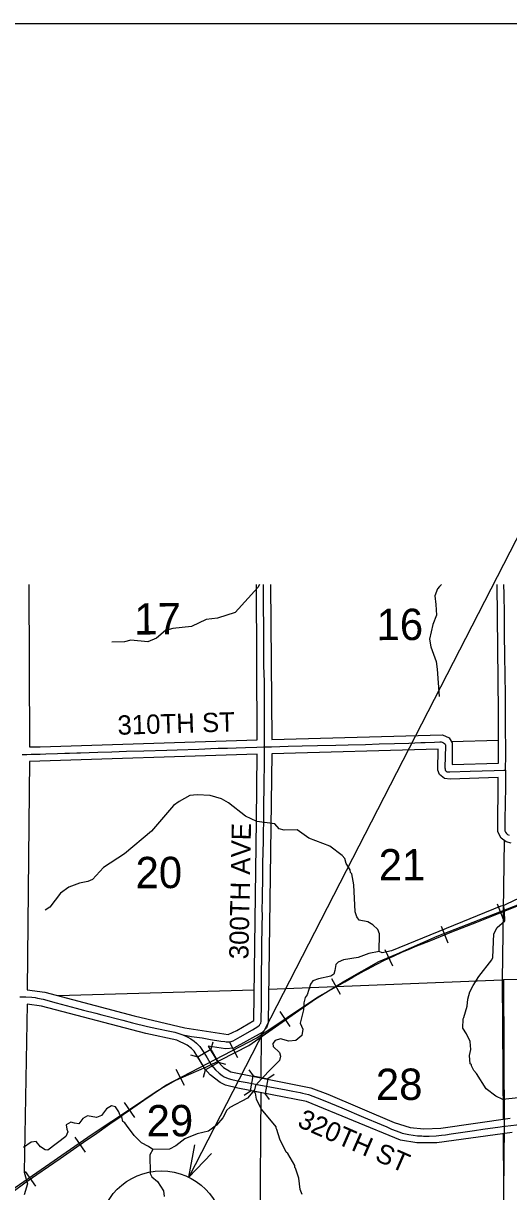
# Model space of a CAD drawing. Extents: x 10133 to 81668, y 7924 to 11018.
# Drawn here: x 11454 to 11756, y 9217 to 9944 of the extents above; entities that cross this region are included whole.
import ezdxf

# ---------------------------------------------------------------- set-up
doc = ezdxf.new("R2010")
doc.units = 0
for name, color, linetype in [('SheetBorder', 7, 'Continuous'), ('tdCoCityStreetMajor', 7, 'Continuous'), ('tdCoCityStreetMinor', 7, 'Continuous'), ('tdCoHydroRiver', 7, 'Continuous'), ('tdCoPriNonDiv', 7, 'Continuous'), ('tdCoRRCL', 7, 'Continuous'), ('tdCoRROwnerTxt', 7, 'Continuous'), ('tdCoShieldCoRte', 7, 'Continuous'), ('tdCoShieldStRte', 7, 'Continuous'), ('tdCoStrucNonDivPri', 7, 'Continuous'), ('tdCoSurfGravel', 7, 'Continuous'), ('tdCoTwpBndryShd', 7, 'Continuous')]:
    doc.layers.add(name, color=color, linetype=linetype)

msp = doc.modelspace()

# ---------------------------------------------------------------- linework, layer by layer
at = {"layer": 'SheetBorder'}
for p, q in [((11832.54, 9762.18), (11557.09, 9226.18)), ((11557.09, 9226.18), (11560.85, 9246.27)), ((11557.09, 9226.18), (11571.23, 9240.94))]:
    msp.add_line(p, q, dxfattribs=at)
msp.add_lwpolyline([(10132.52, 9944.02), (13267.53, 9944.02), (13267.53, 7924.02), (10132.52, 7924.02)], close=True, dxfattribs=at)
msp.add_circle((11540.08, 9191.25), 38.85, dxfattribs=at)
at = {"layer": 'tdCoCityStreetMajor'}
msp.add_lwpolyline([(11604.29, 9506.89), (11604.27, 9513.52), (11604.25, 9522.6), (11604.27, 9534.65), (11603.93, 9544.27), (11603.78, 9555.72), (11603.75, 9572.71), (11603.63, 9577.17), (11603.56, 9588), (11603.56, 9593.54), (11603.56, 9594.91)], dxfattribs=at)
at = {"layer": 'tdCoCityStreetMinor'}
for points in [[(11754.35, 9479.31), (11754.38, 9481.04), (11754.55, 9487.28), (11754.5, 9493.19), (11754.4, 9504.74), (11754.35, 9515.78), (11754.25, 9526.71), (11754.1, 9538.35), (11753.93, 9550.8), (11753.78, 9563.9), (11753.59, 9576.47), (11753.41, 9588.95), (11753.35, 9594.91)], [(11604.23, 9493.82), (11604.15, 9495.44), (11604.32, 9501.58), (11604.3, 9504.77), (11604.29, 9506.89)], [(11453.46, 9489.11), (11454.39, 9489.13), (11456.22, 9489.2), (11459.03, 9489.38), (11464.63, 9489.35), (11468.18, 9489.57), (11475.33, 9489.75), (11479.99, 9489.94), (11482.8, 9489.99), (11487.46, 9490.09), (11489.68, 9490.14), (11500.39, 9490.61), (11509.12, 9490.73), (11518.27, 9491.13), (11529.17, 9491.4), (11543.35, 9491.92), (11549.91, 9492.09), (11563.27, 9492.48), (11570.84, 9492.88), (11575.36, 9493.05), (11581.18, 9493.15), (11586.63, 9493.32), (11592.37, 9493.52), (11599.55, 9493.77), (11603.64, 9493.82), (11604.23, 9493.82)], [(11553.41, 9314.77), (11555.74, 9314.34), (11558.8, 9313.77), (11565.46, 9312.81), (11570.64, 9311.94), (11577.1, 9310.88), (11579.46, 9310.54), (11580.4, 9310.46), (11581.54, 9310.44), (11582.57, 9310.44), (11583.46, 9310.61), (11584.72, 9311.11), (11589.11, 9313.45), (11596.75, 9317.79), (11600.1, 9319.84), (11601.07, 9320.75), (11601.63, 9321.61), (11601.88, 9322.06), (11602.13, 9323.16), (11602.23, 9325.29), (11602.3, 9331.8), (11602.32, 9341.71), (11602.32, 9346.42), (11602.42, 9353.32), (11602.5, 9362.75), (11602.62, 9372.58), (11602.72, 9379.84), (11602.82, 9383.14), (11602.99, 9388.74), (11602.87, 9393.15), (11602.99, 9398.92), (11603.06, 9403.85), (11603.26, 9409.55), (11603.29, 9415.91), (11603.31, 9422.42), (11603.38, 9427.48), (11603.53, 9436.16), (11603.61, 9440.13), (11603.75, 9448.1), (11603.88, 9459.14), (11603.95, 9467.5), (11603.98, 9472.19), (11604.15, 9482.57), (11604.3, 9492.58), (11604.23, 9493.82)], [(11604.23, 9493.82), (11605.29, 9493.82), (11608.57, 9493.96), (11618.93, 9494.31), (11627.73, 9494.51), (11637.2, 9494.65), (11648.7, 9495.02), (11656.27, 9495.07), (11667.09, 9495.44), (11675.58, 9495.69), (11685.14, 9496.04), (11694.02, 9496.23), (11701.52, 9496.53), (11704.21, 9496.6), (11710.05, 9496.87), (11713.5, 9497), (11714.29, 9497), (11714.96, 9496.82), (11715.65, 9496.5), (11716.24, 9496.06), (11716.64, 9495.52), (11716.86, 9494.88), (11716.96, 9494.11), (11716.81, 9488.02), (11716.54, 9480.84), (11716.64, 9480.15), (11716.81, 9479.44), (11717.4, 9478.82), (11718.02, 9478.43), (11719.67, 9478.4), (11732.27, 9478.75), (11747.31, 9479.27), (11753.23, 9479.37), (11754.35, 9479.31)], [(11754.35, 9479.31), (11754.33, 9477.88), (11754.23, 9469.59), (11754.06, 9458), (11753.96, 9449.32), (11753.88, 9442.94), (11753.98, 9441.68), (11754.33, 9440.89), (11754.94, 9440.1), (11755.61, 9439.46), (11756.57, 9438.94)], [(11452, 9338.42), (11453.11, 9338.45), (11455.63, 9338.35), (11459.28, 9338.15), (11461.35, 9337.93), (11462.83, 9337.66), (11466.38, 9336.94), (11474.59, 9334.7), (11477.58, 9333.88), (11486.9, 9331.44), (11491.63, 9330.18), (11499.18, 9328.16), (11503.03, 9327.1), (11515.95, 9323.85), (11521.99, 9322.24), (11531.48, 9319.85), (11537.21, 9318.62), (11545.25, 9317.04), (11548.45, 9316.33), (11550.92, 9315.68), (11553.41, 9314.77)], [(11553.41, 9314.77), (11556.1, 9313.47), (11558.36, 9312.23), (11560.46, 9310.8), (11561.89, 9309.54), (11563.96, 9307.45), (11566.45, 9303.7), (11568.5, 9300.52), (11570.94, 9296.15), (11572.52, 9294.35), (11573.73, 9292.92), (11575.92, 9290.95), (11577.97, 9289.54), (11579.15, 9288.71), (11581.69, 9287.57), (11583.81, 9286.86), (11588.48, 9285.89), (11593.36, 9285.03), (11601.79, 9283.53), (11609.81, 9282.05), (11617.72, 9280.57), (11621.92, 9279.73), (11626.38, 9278.92), (11627.88, 9278.5), (11631.63, 9277.53), (11634.25, 9276.62), (11637.11, 9275.59), (11641.89, 9273.69), (11652.32, 9269.25), (11665.91, 9263.48), (11676.83, 9258.92), (11680.41, 9257.49), (11683.32, 9256.13), (11688.5, 9254.23), (11690.05, 9253.64), (11694.05, 9252.65), (11696.88, 9252.23), (11699.52, 9251.99), (11702.21, 9251.84), (11703.3, 9251.76), (11706.72, 9251.79), (11711.14, 9251.94), (11714.39, 9252.23), (11717.01, 9252.53), (11720.53, 9253.14), (11735.03, 9255.29), (11740.26, 9255.98), (11751.01, 9257.49), (11753.46, 9257.83)]]:
    msp.add_lwpolyline(points, dxfattribs=at)
at = {"layer": 'tdCoHydroRiver'}
for points in [[(11601.23, 9594.91), (11600.02, 9593.14), (11586.08, 9577.51), (11575.01, 9574.01), (11567.92, 9573.18), (11558.76, 9568.77), (11547.17, 9567.62), (11542.69, 9566.37), (11537.09, 9561.54), (11531.68, 9559.31), (11521.01, 9560.32), (11517, 9559.3), (11509.2, 9558.94)], [(11714.45, 9594.91), (11713.2, 9593.62), (11712.04, 9592.18), (11710.22, 9587.88), (11711.02, 9582.45), (11711.37, 9575.83), (11709.09, 9570.11), (11706.88, 9560.83), (11707.91, 9556.11), (11711.14, 9546.93), (11711.69, 9542.21), (11712.93, 9525.18)], [(11675.57, 9366.61), (11675.86, 9377.51), (11674.87, 9380.33), (11671.74, 9383.12), (11668.63, 9384.97), (11663.17, 9386.06), (11661.71, 9388.16), (11660.71, 9391.23), (11659.96, 9408.03), (11658.66, 9414.87), (11657.7, 9415.8), (11657.67, 9417.46), (11655, 9421.44), (11654.24, 9424.5), (11652.55, 9426.37), (11644.87, 9432.16), (11631.76, 9437.15), (11624.58, 9442.24), (11616.53, 9442.1), (11613.43, 9443), (11610.78, 9446.03), (11599.39, 9447.5), (11592.47, 9450.7), (11581.91, 9459.05), (11577.37, 9461.57), (11570.47, 9463.59), (11562.41, 9464.16), (11557.68, 9463.61), (11551.11, 9459.95), (11547.6, 9457.52), (11533.9, 9441.43), (11517.09, 9427.41), (11503.97, 9418.9), (11497.23, 9411.45), (11494.17, 9410.21), (11488.98, 9409.18), (11482.39, 9406.7), (11477.24, 9402.83), (11470.52, 9394.19), (11467.71, 9392.25)], [(11775.19, 9404.04), (11760.54, 9398.66), (11753.23, 9395.15)], [(11753.23, 9395.15), (11751.34, 9394.88), (11683.38, 9366.98), (11677.48, 9365.7), (11675.57, 9366.61)], [(11762.11, 9275.48), (11752.65, 9274.61), (11748.36, 9276.67), (11742.36, 9281.07), (11736.28, 9290.67), (11734.59, 9292.54), (11733.12, 9295.36), (11733.11, 9296.3), (11732.39, 9296.76), (11731.83, 9301.96), (11732.72, 9305.53), (11732.4, 9310.5), (11729.95, 9315.43), (11727.76, 9318.94), (11727.9, 9324.63), (11728.35, 9325.59), (11730.37, 9332.49), (11730.77, 9336.99), (11732.11, 9341.51), (11734.18, 9345.34), (11737.63, 9351.08), (11745.75, 9361.4), (11746.44, 9362.83), (11747.14, 9377.52), (11749.2, 9381.58), (11753.87, 9385.69), (11753.77, 9391.37), (11753.51, 9392.78), (11753.23, 9395.15)], [(11675.57, 9366.61), (11669.2, 9365.32), (11662.61, 9362.84), (11653.4, 9361.5), (11650.11, 9360.03), (11648.71, 9358.58), (11648.07, 9354.78), (11647.4, 9352.4), (11645.52, 9351.19), (11637.97, 9349.64), (11634.44, 9348.4), (11632.82, 9346.24), (11630.8, 9339.58), (11629.64, 9337.9), (11628.75, 9334.57), (11628.59, 9330.3), (11626.36, 9321.98), (11628.08, 9318.22), (11627.43, 9314.42), (11623.7, 9311.28), (11619.44, 9310.73), (11614.21, 9312.3), (11610.91, 9311.3), (11609.52, 9309.38), (11609.55, 9307.49), (11613.64, 9303.77), (11614.15, 9301.41), (11613.49, 9298.79), (11608.37, 9293.5), (11602.55, 9287.48), (11598.6, 9283.15), (11597.93, 9280.54)], [(11597.93, 9280.54), (11593.76, 9275.26), (11582.72, 9269.62), (11580.85, 9267.94), (11578.33, 9263.16), (11574.38, 9258.59), (11569.47, 9254.72), (11562.4, 9253.18), (11554.64, 9249.97), (11549.03, 9245.62), (11545.03, 9243.65), (11534.62, 9243.48)], [(11627.67, 9215.44), (11626.44, 9218.5), (11625.61, 9225.59), (11623.61, 9231.71), (11623.13, 9232.18), (11623.11, 9233.36), (11618.72, 9240.87), (11617.76, 9241.8), (11613.84, 9249.78), (11611.84, 9255.91), (11611.59, 9256.61), (11611.58, 9257.56), (11608.67, 9261.06), (11602.15, 9268.77), (11599.21, 9274.64), (11598.67, 9278.42), (11597.95, 9279.11), (11597.93, 9280.54)], [(11534.62, 9243.48), (11531.98, 9245.33), (11527.68, 9247.63), (11523.11, 9252.05), (11518.26, 9258.6), (11517.29, 9260), (11516.09, 9260.93), (11515.33, 9263.76), (11514.13, 9264.92), (11513.63, 9266.81), (11511.44, 9269.85), (11509.06, 9270.52), (11505.78, 9268.81), (11502.77, 9264.49), (11499.71, 9263.26), (11494.01, 9264.35), (11491.2, 9262.64), (11488.65, 9259.28), (11486.04, 9259.71), (11483.66, 9260.38), (11480.85, 9258.68), (11481.13, 9256.08), (11481.87, 9254.43), (11480.49, 9251.57), (11469.27, 9243.09), (11467.61, 9243.3), (11464.74, 9245.15), (11462.08, 9248.42), (11459.01, 9247.89), (11454.09, 9244.73)], [(11534.62, 9243.48), (11532.78, 9240.13), (11532.98, 9228.53), (11534.19, 9226.42), (11537.56, 9223.4), (11541.44, 9217.78), (11541.74, 9214.24)]]:
    msp.add_lwpolyline(points, dxfattribs=at)
at = {"layer": 'tdCoPriNonDiv'}
msp.add_line((11457.5, 9594.91), (11457.98, 9493.82), dxfattribs=at)
for points in [[(11457.98, 9493.82), (11464.5, 9493.85), (11599.73, 9498.27), (11599.22, 9594.91)], [(11608.07, 9594.91), (11608.73, 9498.47), (11715.05, 9501.43), (11719.2, 9499.45), (11721.11, 9496.35), (11721.12, 9482.94)], [(11721.12, 9482.94), (11749.95, 9483.81), (11749.85, 9515.75), (11749.02, 9594.91)], [(11757.74, 9434.03), (11754.7, 9434.85), (11751.6, 9437.09), (11749.54, 9440.95), (11749.79, 9474.81), (11719.79, 9473.91), (11716.22, 9474.3), (11713.3, 9476.62), (11712.22, 9479.31), (11712.42, 9492.46), (11608.75, 9489.47), (11606.52, 9322.19), (11605.39, 9319.14), (11602.71, 9316.17), (11585.1, 9306.42), (11580.05, 9305.98), (11569.25, 9307.61), (11574.64, 9298.76), (11578.71, 9294.49), (11583.33, 9291.77), (11633.11, 9281.78), (11643.65, 9277.83), (11685.05, 9260.29), (11694.92, 9257.07), (11703.43, 9256.26), (11713.94, 9256.71), (11757.29, 9262.91)], [(11586.94, 9317.39), (11597.65, 9323.76), (11599.26, 9448.16), (11599.75, 9489.27), (11457.94, 9484.8), (11457.66, 9466.01), (11456.51, 9342.8), (11467.57, 9341.28), (11523.12, 9326.6), (11554.6, 9319.13), (11581.58, 9314.94), (11586.94, 9317.39)], [(11758.54, 9254), (11711.55, 9247.46), (11699.1, 9247.51), (11688.97, 9249.27), (11630.33, 9273.22), (11587.57, 9281.49), (11579.86, 9283.46), (11576.55, 9285.03), (11570.5, 9289.79), (11567.36, 9293.43), (11560.46, 9304.6), (11558.8, 9306.27), (11556.02, 9308.39), (11549.57, 9311.39), (11530.39, 9315.49), (11465.34, 9332.56), (11456.41, 9333.8), (11454.66, 9229.41), (11456.75, 9222.11), (11454.63, 9215.25)]]:
    msp.add_lwpolyline(points, dxfattribs=at)
at = {"layer": 'tdCoRRCL'}
for p, q in [((11753.37, 9385.52), (11749.23, 9395.98)), ((11718.51, 9371.72), (11714.36, 9382.18)), ((11684.2, 9357.39), (11679.48, 9367.6)), ((11651.61, 9339.79), (11646.09, 9349.6)), ((11620.3, 9320.01), (11614.03, 9329.35)), ((11587.68, 9300.38), (11582.51, 9310.37)), ((11568.06, 9294.84), (11577.07, 9299.13)), ((11554.37, 9283.15), (11549.2, 9293.14)), ((11523.46, 9263.32), (11517.06, 9272.57)), ((11492.71, 9241.84), (11486.33, 9251.1)), ((11461.92, 9220.55), (11455.42, 9229.74))]:
    msp.add_line(p, q, dxfattribs=at)
for points in [[(11577.07, 9299.13), (11594.5, 9308.16), (11635.99, 9337.16), (11654.28, 9348.37), (11675.39, 9360.38), (11686.92, 9365.1), (11711.76, 9376.15), (11777.93, 9401.93)], [(11447.66, 9217.37), (11455.03, 9222.58), (11462.41, 9227.79), (11477.01, 9237.85), (11491.62, 9247.92), (11499.76, 9253.64), (11507.9, 9259.36), (11514.29, 9263.8), (11516.19, 9265.12), (11518.09, 9266.44), (11529.06, 9274.03), (11540.03, 9281.62), (11542.86, 9283.52), (11599.49, 9312.82), (11637.31, 9338.2), (11645.76, 9342.96), (11654.22, 9347.72), (11659.29, 9350.63), (11664.36, 9353.54), (11666.39, 9354.62), (11668.41, 9355.7), (11673.86, 9358.51), (11679.3, 9361.32), (11684.53, 9363.74), (11689.76, 9366.16), (11693.87, 9367.89), (11697.98, 9369.62), (11702.33, 9371.35), (11706.68, 9373.07), (11713.81, 9375.91), (11720.94, 9378.74), (11736.49, 9384.89), (11752.05, 9391.05), (11766.65, 9396.81)], [(11408.96, 9192.14), (11496.88, 9252.86), (11521.5, 9269.09), (11537.38, 9279.92), (11549.05, 9286.44), (11568.06, 9294.84)]]:
    msp.add_lwpolyline(points, dxfattribs=at)
at = {"layer": 'tdCoShieldCoRte'}
for points in [[(11558.23, 9302.29), (11562.76, 9301.06), (11570.9, 9305.74)], [(11572.12, 9310.27), (11570.9, 9305.74), (11575.58, 9297.6)], [(11566.24, 9288.49), (11567.44, 9292.93), (11562.76, 9301.06)], [(11580.1, 9296.38), (11575.58, 9297.6), (11567.44, 9292.93)], [(11591.57, 9277.29), (11595.44, 9279.94), (11597.17, 9289.17)], [(11594.51, 9293.04), (11597.17, 9289.17), (11606.39, 9287.45)], [(11610.26, 9290.1), (11606.39, 9287.45), (11604.67, 9278.22)], [(11607.26, 9274.43), (11604.67, 9278.22), (11595.44, 9279.94)]]:
    msp.add_lwpolyline(points, dxfattribs=at)
at = {"layer": 'tdCoStrucNonDivPri'}
for points in [[(11720.72, 9497.28), (11749.97, 9498.15)], [(11753.54, 9435.5), (11752.27, 9349.01)], [(11606.9, 9343.15), (11752.27, 9349.01)], [(11752.27, 9349.01), (11753.11, 9349.02)], [(11752.27, 9349.01), (11752.82, 9262.27)], [(11475.59, 9339.13), (11597.85, 9342.83)], [(11602.16, 9315.85), (11601.95, 9287.99)], [(11601.88, 9278.86), (11601.26, 9197.63)], [(11752.87, 9253.22), (11753.08, 9219.84)]]:
    msp.add_lwpolyline(points, dxfattribs=at)
at = {"layer": 'tdCoSurfGravel'}
msp.add_lwpolyline([(11905.17, 9206.37), (11905.22, 9227.48), (11905.09, 9246.02), (11905, 9248.71), (11904.97, 9250.05), (11905.02, 9257.72), (11905.1, 9275.72), (11904.44, 9350.85), (11856.16, 9350.39), (11830.5, 9350.06), (11805.56, 9349.73), (11753.1, 9349.04), (11753.46, 9257.83), (11752.84, 9195.79)], dxfattribs=at)
at = {"layer": 'tdCoTwpBndryShd'}
msp.add_lwpolyline([(11753.46, 9257.83), (11754, 9257.9), (11761.1, 9258.82), (11767.39, 9259.66), (11774.96, 9260.67), (11776.98, 9260.94), (11779, 9261.21), (11782.28, 9261.55), (11784.04, 9261.74), (11788.8, 9262.16), (11790.25, 9262.34), (11790.99, 9262.38)], dxfattribs=at)

# ---------------------------------------------------------------- texts
at = {"layer": 'tdCoRROwnerTxt'}
for s, rotation, p in [('17', 0.22815, (11523.18, 9563.77)), ('16', 0.2289, (11674.04, 9560.27)), ('21', 0.22892, (11675.39, 9410.77)), ('20', 0.22818, (11524, 9405.94)), ('28', 0.22894, (11673.62, 9274.17)), ('29', 0.22824, (11530.88, 9251.54))]:
    msp.add_text(s, height=19.5, rotation=rotation, dxfattribs=at).set_placement(p)
at = {"layer": 'tdCoShieldStRte'}
for s, rotation, p in [('310TH ST', 1.68736, (11512.89, 9501.4)), ('300TH AVE', 88.8553, (11594.2, 9361.67)), ('320TH ST', 336.42013, (11624.12, 9257.92))]:
    msp.add_text(s, height=12, rotation=rotation, dxfattribs=at).set_placement(p)

doc.saveas('drawing.dxf')
